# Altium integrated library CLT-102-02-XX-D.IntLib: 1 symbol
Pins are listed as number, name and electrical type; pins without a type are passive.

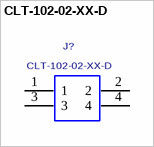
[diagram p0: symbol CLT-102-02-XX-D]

## CLT-102-02-XX-D
designator J?
LOW PROFILE SOCKET STRIP, 2mm PITCH, 4 PINS.; MANUFACTURER: SAMTEC
footprint CLT-102-02-XX-D
pins: 1, 2, 3, 4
